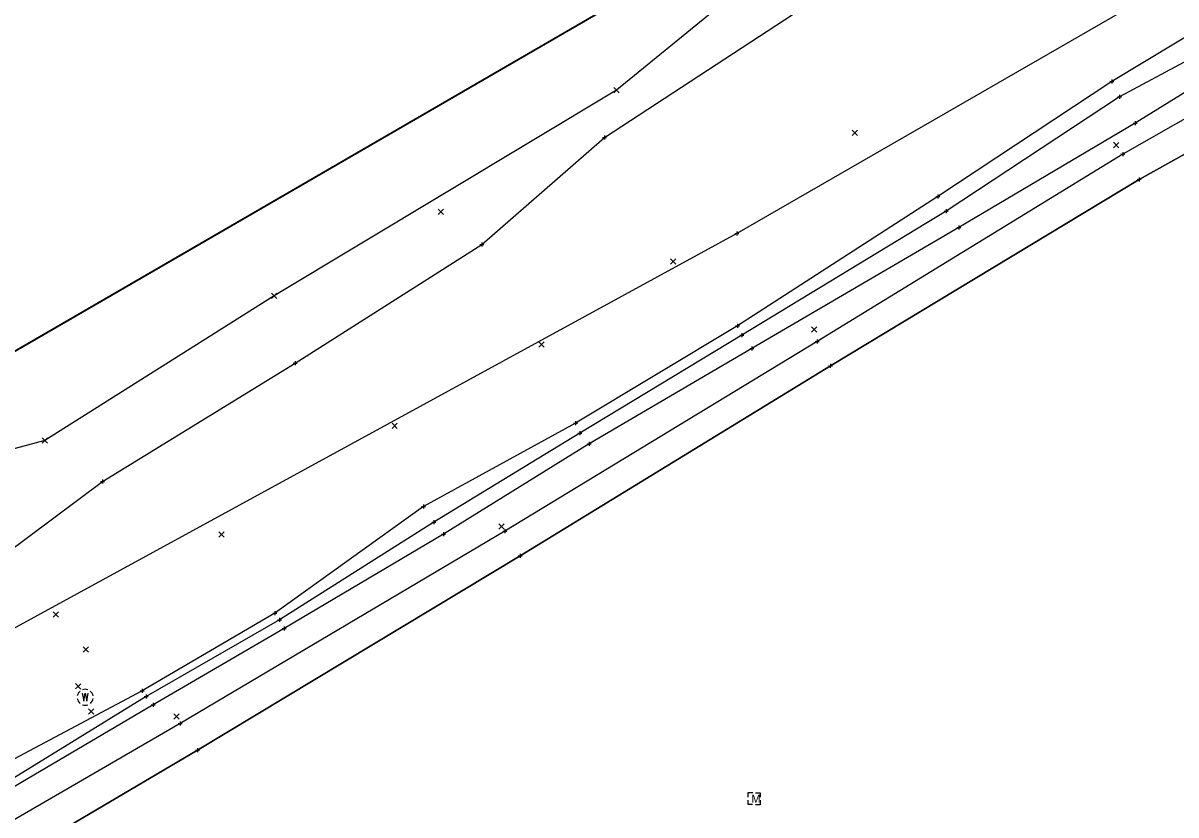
# Model space of a CAD drawing. Extents: x 142461 to 147261, y 511126 to 514697.
# Drawn here: x 146413 to 146701.2, y 514246.2 to 514444.2 of the extents above; entities that cross this region are included whole.
import ezdxf

# ---------------------------------------------------------------- set-up
doc = ezdxf.new("R2010")
doc.units = 0
for name, color, linetype in [('DR_X_Ditch', 7, 'Continuous'), ('PM_X_Surveyed_Line', 7, 'Continuous'), ('PV_X_EOP', 7, 'Continuous'), ('RD_X_Fence', 7, 'Continuous'), ('SV_X_Mon_Cells_Found', 7, 'Continuous'), ('SV_X_Original_Ground', 7, 'Continuous'), ('SV_X_Random_Point', 7, 'Continuous'), ('SV_X_Shot_Marker', 7, 'Continuous'), ('SV_X_Toe_of_Slope', 7, 'Continuous'), ('SV_X_Top_of_Bank', 7, 'Continuous'), ('UT_X_Water_Cells', 7, 'Continuous'), ('VG_X_Tree_Line_Lt', 7, 'Continuous')]:
    doc.layers.add(name, color=color, linetype=linetype)

msp = doc.modelspace()

# ---------------------------------------------------------------- linework, layer by layer
at = {"layer": 'DR_X_Ditch'}
msp.add_lwpolyline([(146972.34, 514593.46), (146929.62, 514568.11), (146890.14, 514544.2), (146843.47, 514516.97), (146803.26, 514492.13), (146758.98, 514467.66), (146720.48, 514443.67), (146687.05, 514425.75), (146643.71, 514397.16), (146592.68, 514366.15), (146552.17, 514341.71), (146515.69, 514319.43), (146477.06, 514294.98), (146443.78, 514275.87), (146406.32, 514252.85), (146359.05, 514229.18), (146314.83, 514201.54), (146274.19, 514179.48), (146241.44, 514164.3), (146203.29, 514141.37), (146157.06, 514121.98), (146117.23, 514101.58)], dxfattribs=at)
at = {"layer": 'PM_X_Surveyed_Line'}
msp.add_lwpolyline([(146936.5, 514545.38), (146901.96, 514523.88), (146817.16, 514475.05), (146691.97, 514405.14), (146614.79, 514358.5), (146537.21, 514310.98), (146456.62, 514262.43), (146373.73, 514213.61), (146290.32, 514166.13), (146211.14, 514122.87), (146123.97, 514079.6), (146039.98, 514041.62), (145963.95, 514008.93), (145842.42, 513958.73), (145748.84, 513919.85), (145682.8, 513887.45), (145618.56, 513849.17)], dxfattribs=at)
at = {"layer": 'PV_X_EOP'}
for p, q in [((146812.56, 514482.69), (146687.92, 514411.47)), ((146687.92, 514411.47), (146611.45, 514364.61)), ((146611.45, 514364.61), (146533.4, 514317.15)), ((146533.4, 514317.15), (146452.24, 514269.11)), ((146452.24, 514269.11), (146369.12, 514220.8))]:
    msp.add_line(p, q, dxfattribs=at)
at = {"layer": 'RD_X_Fence'}
msp.add_lwpolyline([(146900.86, 514646.23), (146332.42, 514316.7), (145890.39, 514050.56), (145774.93, 514232.06), (145655.09, 514421.49), (144949.64, 513970.2), (144936.36, 513451.75), (144101.94, 512896.99), (144046.01, 512862.62), (143758.01, 512670.87), (143619.22, 512579.24), (143474.12, 512483.15), (143357.83, 512406.57), (143315.36, 512377.21)], dxfattribs=at)
at = {"layer": 'SV_X_Mon_Cells_Found'}
for points in [[(146594.24, 514250.69), (146594.25, 514251.81), (146595.37, 514251.8)], [(146596.11, 514251.79), (146597.25, 514251.78), (146597.24, 514250.66)], [(146595.34, 514248.8), (146594.22, 514248.81), (146594.23, 514249.93)], [(146597.23, 514249.9), (146597.22, 514248.78), (146596.08, 514248.79)]]:
    msp.add_lwpolyline(points, dxfattribs=at)
at = {"layer": 'SV_X_Original_Ground'}
for points in [[(146764.79, 514555.47), (146687.58, 514514.51), (146654.76, 514494.88), (146609.54, 514466.88), (146561.33, 514427.46), (146475.78, 514376.04), (146418.4, 514339.85), (146332.42, 514316.7), (146296.13, 514262.85), (146244.27, 514241.18), (146215.75, 514234.07), (146139.46, 514184.74), (146098.44, 514162.17)], [(146123.97, 514079.6), (146211.14, 514122.87), (146290.32, 514166.13), (146373.73, 514213.61), (146456.62, 514262.43), (146537.21, 514310.98), (146614.79, 514358.5), (146691.97, 514405.14), (146817.16, 514475.05)]]:
    msp.add_lwpolyline(points, dxfattribs=at)
at = {"layer": 'SV_X_Random_Point'}
for p, q in [((146560.67, 514426.79), (146562, 514428.13)), ((146560.67, 514428.13), (146562, 514426.79)), ((146620.27, 514416.1), (146621.6, 514417.43)), ((146620.27, 514417.43), (146621.6, 514416.1)), ((146685.59, 514413.06), (146686.94, 514414.38)), ((146685.6, 514414.4), (146686.92, 514413.05)), ((146516.75, 514396.36), (146518.08, 514397.69)), ((146516.75, 514397.69), (146518.08, 514396.36)), ((146574.82, 514383.95), (146576.15, 514385.28)), ((146574.82, 514385.28), (146576.15, 514383.95)), ((146475.11, 514375.37), (146476.45, 514376.7)), ((146475.11, 514376.7), (146476.45, 514375.37)), ((146610.05, 514366.93), (146611.4, 514368.25)), ((146610.07, 514368.27), (146611.39, 514366.92)), ((146541.95, 514363.22), (146543.28, 514364.55)), ((146541.95, 514364.55), (146543.28, 514363.22)), ((146505.21, 514342.84), (146506.54, 514344.18)), ((146505.21, 514344.18), (146506.54, 514342.84)), ((146417.73, 514339.18), (146419.07, 514340.51)), ((146417.73, 514340.51), (146419.07, 514339.18)), ((146531.89, 514317.68), (146533.23, 514319)), ((146531.9, 514319.01), (146533.22, 514317.67)), ((146461.9, 514315.66), (146463.23, 514317)), ((146461.9, 514317), (146463.23, 514315.66)), ((146420.52, 514295.66), (146421.85, 514296.99)), ((146420.52, 514296.99), (146421.85, 514295.66)), ((146427.97, 514286.89), (146429.3, 514288.22)), ((146427.97, 514288.22), (146429.3, 514286.89)), ((146426.08, 514277.72), (146427.42, 514279.04)), ((146426.09, 514279.06), (146427.41, 514277.71)), ((146429.36, 514271.45), (146430.71, 514272.77)), ((146429.37, 514272.78), (146430.69, 514271.43)), ((146450.7, 514270.18), (146452.04, 514271.5)), ((146450.71, 514271.52), (146452.03, 514270.17))]:
    msp.add_line(p, q, dxfattribs=at)
at = {"layer": 'SV_X_Shot_Marker'}
for p, q in [((146684.63, 514429.62), (146685.63, 514429.62)), ((146685.13, 514430.12), (146685.13, 514429.12)), ((146685.13, 514429.62), (146685.13, 514429.62)), ((146686.55, 514425.75), (146687.55, 514425.75)), ((146687.05, 514426.25), (146687.05, 514425.25)), ((146687.05, 514425.75), (146687.05, 514425.75)), ((146690.51, 514419.15), (146691.51, 514419.15)), ((146691.01, 514419.65), (146691.01, 514418.65)), ((146691.01, 514419.15), (146691.01, 514419.15)), ((146558.29, 514416.09), (146558.29, 514415.09)), ((146557.79, 514415.59), (146558.79, 514415.59)), ((146558.29, 514415.59), (146558.29, 514415.59)), ((146687.42, 514411.48), (146688.42, 514411.47)), ((146687.93, 514411.97), (146687.92, 514410.97)), ((146687.92, 514411.47), (146687.92, 514411.47)), ((146691.47, 514405.15), (146692.47, 514405.14)), ((146691.97, 514405.64), (146691.96, 514404.64)), ((146691.97, 514405.14), (146691.97, 514405.14)), ((146641.12, 514400.83), (146642.12, 514400.83)), ((146641.62, 514401.33), (146641.62, 514400.33)), ((146641.62, 514400.83), (146641.62, 514400.83)), ((146643.21, 514397.16), (146644.21, 514397.16)), ((146643.71, 514397.66), (146643.71, 514396.66)), ((146643.71, 514397.16), (146643.71, 514397.16)), ((146646.41, 514393.1), (146647.41, 514393.1)), ((146646.91, 514393.6), (146646.91, 514392.6)), ((146646.91, 514393.1), (146646.91, 514393.1)), ((146590.94, 514391.6), (146591.94, 514391.59)), ((146591.45, 514392.1), (146591.44, 514391.1)), ((146591.44, 514391.6), (146591.44, 514391.6)), ((146527.2, 514388.82), (146528.2, 514388.82)), ((146527.7, 514389.32), (146527.7, 514388.32)), ((146527.7, 514388.82), (146527.7, 514388.82)), ((146591.07, 514368.49), (146592.07, 514368.49)), ((146591.57, 514368.99), (146591.57, 514367.99)), ((146591.57, 514368.49), (146591.57, 514368.49)), ((146592.18, 514366.15), (146593.18, 514366.15)), ((146592.68, 514366.65), (146592.68, 514365.65)), ((146592.68, 514366.15), (146592.68, 514366.15)), ((146610.95, 514364.61), (146611.95, 514364.6)), ((146611.46, 514365.11), (146611.45, 514364.11)), ((146611.45, 514364.61), (146611.45, 514364.61)), ((146594.65, 514362.87), (146595.65, 514362.87)), ((146595.15, 514363.37), (146595.15, 514362.37)), ((146595.15, 514362.87), (146595.15, 514362.87)), ((146480.47, 514359.22), (146481.47, 514359.22)), ((146480.97, 514359.72), (146480.97, 514358.72)), ((146480.97, 514359.22), (146480.97, 514359.22)), ((146614.29, 514358.51), (146615.29, 514358.5)), ((146614.79, 514359), (146614.78, 514358)), ((146614.79, 514358.5), (146614.79, 514358.5)), ((146550.55, 514344.21), (146551.55, 514344.21)), ((146551.05, 514344.71), (146551.05, 514343.71)), ((146551.05, 514344.21), (146551.05, 514344.21)), ((146551.67, 514341.71), (146552.67, 514341.71)), ((146552.17, 514342.21), (146552.17, 514341.21)), ((146552.17, 514341.71), (146552.17, 514341.71)), ((146553.98, 514338.98), (146554.98, 514338.98)), ((146554.48, 514339.48), (146554.48, 514338.48)), ((146554.48, 514338.98), (146554.48, 514338.98)), ((146432.32, 514329.56), (146433.32, 514329.56)), ((146432.82, 514330.06), (146432.82, 514329.06)), ((146432.82, 514329.56), (146432.82, 514329.56)), ((146513.05, 514323.81), (146513.05, 514322.81)), ((146512.55, 514323.31), (146513.55, 514323.31)), ((146513.05, 514323.31), (146513.05, 514323.31)), ((146515.19, 514319.43), (146516.19, 514319.43)), ((146515.69, 514319.93), (146515.69, 514318.93)), ((146515.69, 514319.43), (146515.69, 514319.43)), ((146517.6, 514316.46), (146518.6, 514316.46)), ((146518.1, 514316.96), (146518.1, 514315.96)), ((146518.1, 514316.46), (146518.1, 514316.46)), ((146532.9, 514317.15), (146533.9, 514317.14)), ((146533.41, 514317.65), (146533.4, 514316.65)), ((146533.4, 514317.15), (146533.4, 514317.15)), ((146536.71, 514310.98), (146537.71, 514310.97)), ((146537.22, 514311.48), (146537.21, 514310.48)), ((146537.21, 514310.98), (146537.21, 514310.98)), ((146475.41, 514296.65), (146476.41, 514296.65)), ((146475.91, 514297.15), (146475.91, 514296.15)), ((146475.91, 514296.65), (146475.91, 514296.65)), ((146476.56, 514294.98), (146477.56, 514294.98)), ((146477.06, 514295.48), (146477.06, 514294.48)), ((146477.06, 514294.98), (146477.06, 514294.98)), ((146477.78, 514292.87), (146478.78, 514292.87)), ((146478.28, 514293.37), (146478.28, 514292.37)), ((146478.28, 514292.87), (146478.28, 514292.87)), ((146442.74, 514277.78), (146442.74, 514276.78)), ((146442.24, 514277.28), (146443.24, 514277.28)), ((146442.74, 514277.28), (146442.74, 514277.28)), ((146443.28, 514275.87), (146444.28, 514275.87)), ((146443.78, 514276.37), (146443.78, 514275.37)), ((146443.78, 514275.87), (146443.78, 514275.87)), ((146445.02, 514273.79), (146446.02, 514273.79)), ((146445.52, 514274.29), (146445.52, 514273.29)), ((146445.52, 514273.79), (146445.52, 514273.79)), ((146451.74, 514269.12), (146452.74, 514269.11)), ((146452.25, 514269.61), (146452.24, 514268.61)), ((146452.24, 514269.11), (146452.24, 514269.11)), ((146456.12, 514262.43), (146457.12, 514262.42)), ((146456.62, 514262.93), (146456.61, 514261.93)), ((146456.62, 514262.43), (146456.62, 514262.43))]:
    msp.add_line(p, q, dxfattribs=at)
at = {"layer": 'SV_X_Toe_of_Slope'}
msp.add_lwpolyline([(146970.6, 514596.2), (146927.77, 514571.57), (146889.17, 514547.24), (146841.58, 514521.63), (146801.56, 514496.04), (146755.27, 514471.98), (146717.39, 514449.03), (146685.13, 514429.62), (146641.62, 514400.83), (146591.57, 514368.49), (146551.05, 514344.21), (146513.05, 514323.31), (146475.91, 514296.65), (146442.74, 514277.28), (146404.2, 514256.75), (146356.57, 514232.52), (146313.71, 514204.04), (146271.47, 514184.93), (146237.91, 514171.61), (146201.18, 514147.19), (146154.66, 514127.64), (146115.64, 514106.77)], dxfattribs=at)
at = {"layer": 'SV_X_Top_of_Bank'}
for points in [[(146110.05, 514143.01), (146152.44, 514166.06), (146173.07, 514173.35), (146209.92, 514197.78), (146220.62, 514206.29), (146246.44, 514222.32), (146302.22, 514248.8), (146337.62, 514266.44), (146368.17, 514282.74), (146395.91, 514302.05), (146432.82, 514329.56), (146480.97, 514359.22), (146527.7, 514388.82), (146558.29, 514415.59), (146612, 514450.74), (146657.74, 514482.92), (146689.43, 514508.5), (146727.89, 514529.91), (146764.79, 514555.47), (146807.06, 514577.35), (146848.65, 514601.59), (146910.75, 514629.75)], [(146977.31, 514587.49), (146933.53, 514561.2), (146894.23, 514537.47), (146847.45, 514510.07), (146807.46, 514485.33), (146762.55, 514460.95), (146723.94, 514439.52), (146691.01, 514419.15), (146646.91, 514393.1), (146595.15, 514362.87), (146554.48, 514338.98), (146518.1, 514316.46), (146478.28, 514292.87), (146445.52, 514273.79), (146407.72, 514251.54), (146360.74, 514225.24), (146316.11, 514200.12), (146276.34, 514176.03), (146243.57, 514158.61), (146205.44, 514136.54), (146159.97, 514113.67), (146119.4, 514094.6)]]:
    msp.add_lwpolyline(points, dxfattribs=at)
at = {"layer": 'UT_X_Water_Cells'}
msp.add_line((146428.51, 514275.65), (146428.51, 514275.65), dxfattribs=at)
msp.add_lwpolyline([(146427.77, 514276.65), (146428.14, 514274.65), (146428.51, 514276.65), (146428.88, 514274.65), (146429.25, 514276.65)], dxfattribs=at)
for start, end in [(70.0577, 110.1061), (130.0806, 170.0721), (190.0169, 230.0392), (10.0169, 50.0392), (310.0114, 350.0264), (250.0577, 290.0473)]:
    msp.add_arc((146428.51, 514275.65), 2, start, end, dxfattribs=at)
at = {"layer": 'VG_X_Tree_Line_Lt'}
for points in [[(146296.11, 514330.66), (146332.42, 514316.7), (146900.86, 514646.22)], [(146913.71, 514577.37), (146591.44, 514391.6), (146192.98, 514174.02), (145890.39, 514050.56)]]:
    msp.add_lwpolyline(points, dxfattribs=at)

# ---------------------------------------------------------------- texts
at = {"layer": 'SV_X_Mon_Cells_Found'}
msp.add_text('M', height=2, rotation=359.4086, dxfattribs=at).set_placement((146595.06, 514249.3))

doc.saveas('drawing.dxf')
